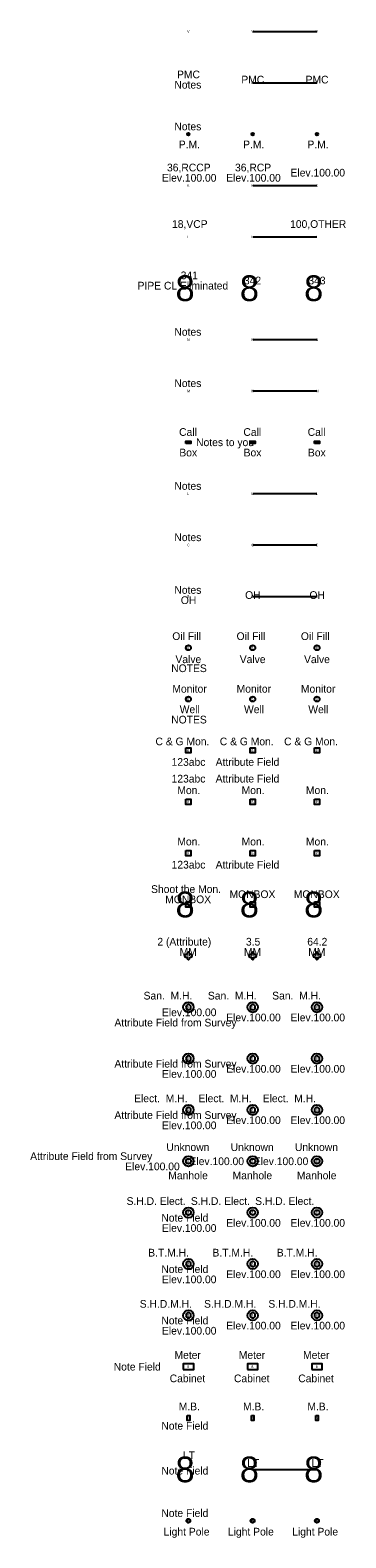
# Model space of a CAD drawing. Extents: x 40011 to 50684, y 49949 to 72236.
# Drawn here: x 50438 to 50561, y 51773 to 52360 of the extents above; entities that cross this region are included whole.
import ezdxf

# ---------------------------------------------------------------- set-up
doc = ezdxf.new("R2010")
doc.units = 0
for name, color, linetype in [('10', 7, 'Continuous'), ('12', 7, 'Continuous'), ('13', 7, 'Continuous'), ('15', 7, 'Continuous'), ('16', 7, 'Continuous'), ('17', 7, 'Continuous'), ('2', 7, 'Continuous'), ('20', 7, 'Continuous'), ('41', 7, 'Continuous'), ('44', 7, 'Continuous'), ('49', 7, 'Continuous'), ('5', 7, 'Continuous'), ('50', 7, 'Continuous'), ('56', 7, 'Continuous'), ('9', 7, 'Continuous')]:
    doc.layers.add(name, color=color, linetype=linetype)

msp = doc.modelspace()

# ---------------------------------------------------------------- linework, layer by layer
at = {"layer": '10'}
for p, q in [((50525, 52300), (50550, 52300)), ((50525, 52280), (50550, 52280))]:
    msp.add_line(p, q, dxfattribs=at)
at = {"layer": '12'}
msp.add_line((50525, 52360), (50550, 52360), dxfattribs=at)
for centre, radius in [((50500, 51940), 2), ((50525, 51940), 2), ((50550, 51940), 2), ((50500, 51900), 2), ((50500, 51900), 1), ((50525, 51900), 2), ((50525, 51900), 1), ((50550, 51900), 2), ((50550, 51900), 1)]:
    msp.add_circle(centre, radius, dxfattribs=at)
for centre, start, end in [((50500, 51940), 360, 180), ((50500, 51940), 180, 0), ((50525, 51940), 360, 180), ((50525, 51940), 180, 0), ((50550, 51940), 360, 180), ((50550, 51940), 180, 0)]:
    msp.add_arc(centre, 1, start, end, dxfattribs=at)
at = {"layer": '13'}
for centre in [(50500, 51880), (50525, 51880), (50550, 51880)]:
    msp.add_circle(centre, 2, dxfattribs=at)
for centre, start, end in [((50500, 51880), 0, 180), ((50525, 51880), 0, 180), ((50550, 51880), 0, 180), ((50500, 51880), 180, 0), ((50525, 51880), 180, 0), ((50550, 51880), 180, 0)]:
    msp.add_arc(centre, 1, start, end, dxfattribs=at)
at = {"layer": '15'}
for centre in [(50500, 52100), (50525, 52100), (50550, 52100)]:
    msp.add_circle(centre, 1, dxfattribs=at)
at = {"layer": '16'}
for centre in [(50500, 51980), (50525, 51980), (50550, 51980)]:
    msp.add_circle(centre, 2, dxfattribs=at)
for centre, start, end in [((50500, 51980), 360, 180), ((50525, 51980), 360, 180), ((50550, 51980), 360, 180), ((50500, 51980), 180, 0), ((50525, 51980), 180, 0), ((50550, 51980), 180, 0)]:
    msp.add_arc(centre, 1, start, end, dxfattribs=at)
at = {"layer": '17'}
msp.add_line((50525, 52340), (50550, 52340), dxfattribs=at)
at = {"layer": '2'}
for p, q in [((50525, 52240), (50550, 52240)), ((50525, 52220), (50550, 52220)), ((50525, 52180), (50550, 52180))]:
    msp.add_line(p, q, dxfattribs=at)
at = {"layer": '20'}
for points in [[(50497.95, 51838.95), (50502.05, 51838.95), (50502.05, 51841.05), (50497.95, 51841.05)], [(50522.95, 51838.95), (50527.05, 51838.95), (50527.05, 51841.05), (50522.95, 51841.05)], [(50547.95, 51838.95), (50552.05, 51838.95), (50552.05, 51841.05), (50547.95, 51841.05)]]:
    msp.add_lwpolyline(points, close=True, dxfattribs=at)
at = {"layer": '5'}
for p, q in [((50525, 52160), (50550, 52160)), ((50525, 52140), (50550, 52140)), ((50499.5, 52000.5), (50499, 52000.5)), ((50499, 51999.5), (50499.5, 51999.5)), ((50499.5, 52001), (50499.5, 52000.5)), ((50499.5, 51999.5), (50499.5, 51999)), ((50500.5, 52000.5), (50500.5, 52001)), ((50501, 52000.5), (50500.5, 52000.5)), ((50500.5, 51999), (50500.5, 51999.5)), ((50500.5, 51999.5), (50501, 51999.5)), ((50524.5, 52000.5), (50524, 52000.5)), ((50524, 51999.5), (50524.5, 51999.5)), ((50524.5, 52001), (50524.5, 52000.5)), ((50524.5, 51999.5), (50524.5, 51999)), ((50525.5, 52000.5), (50525.5, 52001)), ((50526, 52000.5), (50525.5, 52000.5)), ((50525.5, 51999), (50525.5, 51999.5)), ((50525.5, 51999.5), (50526, 51999.5)), ((50549.5, 52000.5), (50549, 52000.5)), ((50549, 51999.5), (50549.5, 51999.5)), ((50549.5, 52001), (50549.5, 52000.5)), ((50549.5, 51999.5), (50549.5, 51999)), ((50550.5, 52000.5), (50550.5, 52001)), ((50551, 52000.5), (50550.5, 52000.5)), ((50550.5, 51999), (50550.5, 51999.5)), ((50550.5, 51999.5), (50551, 51999.5)), ((50525, 51800), (50550, 51800))]:
    msp.add_line(p, q, dxfattribs=at)
for points in [[(50499, 52199.5), (50499, 52200.5), (50501, 52200.5), (50501, 52199.5)], [(50524, 52199.5), (50524, 52200.5), (50526, 52200.5), (50526, 52199.5)], [(50549, 52199.5), (50549, 52200.5), (50551, 52200.5), (50551, 52199.5)], [(50499, 52081), (50501, 52081), (50501, 52079), (50499, 52079)], [(50524, 52081), (50526, 52081), (50526, 52079), (50524, 52079)], [(50549, 52081), (50551, 52081), (50551, 52079), (50549, 52079)], [(50499, 52061), (50501, 52061), (50501, 52059), (50499, 52059)], [(50524, 52061), (50526, 52061), (50526, 52059), (50524, 52059)], [(50549, 52061), (50551, 52061), (50551, 52059), (50549, 52059)], [(50499, 52041), (50501, 52041), (50501, 52039), (50499, 52039)], [(50524, 52041), (50526, 52041), (50526, 52039), (50524, 52039)], [(50549, 52041), (50551, 52041), (50551, 52039), (50549, 52039)], [(50499, 52021), (50501, 52021), (50501, 52019), (50499, 52019)], [(50524, 52021), (50526, 52021), (50526, 52019), (50524, 52019)], [(50549, 52021), (50551, 52021), (50551, 52019), (50549, 52019)], [(50499.5, 51821), (50500.5, 51821), (50500.5, 51819), (50499.5, 51819)], [(50524.5, 51821), (50525.5, 51821), (50525.5, 51819), (50524.5, 51819)], [(50549.5, 51821), (50550.5, 51821), (50550.5, 51819), (50549.5, 51819)]]:
    msp.add_lwpolyline(points, close=True, dxfattribs=at)
for centre, radius in [((50500, 52320), 0.5), ((50525, 52320), 0.5), ((50550, 52320), 0.5), ((50500, 52120), 1), ((50525, 52120), 1), ((50550, 52120), 1), ((50500, 51780), 0.75), ((50525, 51780), 0.75), ((50550, 51780), 0.75)]:
    msp.add_circle(centre, radius, dxfattribs=at)
for centre, start, end in [((50499, 52000), 90, 270), ((50500, 52001), 360, 180), ((50500, 51999), 180, 0), ((50501, 52000), 270, 90), ((50524, 52000), 90, 270), ((50525, 52001), 360, 180), ((50525, 51999), 180, 0), ((50526, 52000), 270, 90), ((50549, 52000), 90, 270), ((50550, 52001), 360, 180), ((50550, 51999), 180, 0), ((50551, 52000), 270, 90)]:
    msp.add_arc(centre, 0.5, start, end, dxfattribs=at)
at = {"layer": '56'}
for centre, radius in [((50500, 51920), 2), ((50500, 51920), 1), ((50525, 51920), 2), ((50525, 51920), 1), ((50550, 51920), 2), ((50550, 51920), 1)]:
    msp.add_circle(centre, radius, dxfattribs=at)
at = {"layer": '9'}
for centre in [(50500, 51960), (50525, 51960), (50550, 51960), (50500, 51860), (50525, 51860), (50550, 51860)]:
    msp.add_circle(centre, 2, dxfattribs=at)
for centre, start, end in [((50500, 51960), 360, 180), ((50500, 51960), 180, 0), ((50525, 51960), 360, 180), ((50525, 51960), 180, 0), ((50550, 51960), 360, 180), ((50550, 51960), 180, 0), ((50500, 51860), 360, 180), ((50500, 51860), 180, 0), ((50525, 51860), 360, 180), ((50525, 51860), 180, 0), ((50550, 51860), 360, 180), ((50550, 51860), 180, 0)]:
    msp.add_arc(centre, 1, start, end, dxfattribs=at)

# ---------------------------------------------------------------- texts
at = {"layer": '12'}
for s, p in [('Elect.  M.H.', (50478.9, 51943)), ('Elect.  M.H.', (50503.9, 51943)), ('Elect.  M.H.', (50528.9, 51943)), ('S.H.D. Elect.', (50475.96, 51903)), ('S.H.D. Elect.', (50500.96, 51903)), ('S.H.D. Elect.', (50525.96, 51903))]:
    msp.add_text(s, height=3, rotation=360, dxfattribs=at).set_placement(p)
at = {"layer": '13'}
for p in [(50484.37, 51882.9), (50509.37, 51882.9), (50534.37, 51882.9)]:
    msp.add_text('B.T.M.H.', height=3, rotation=360, dxfattribs=at).set_placement(p)
at = {"layer": '15'}
for s, p in [('Monitor', (50493.76, 52102.5)), ('Monitor', (50518.76, 52102.5)), ('Monitor', (50543.76, 52102.5)), ('Well', (50496.63, 52094.5)), ('Well', (50521.63, 52094.5)), ('Well', (50546.63, 52094.5))]:
    msp.add_text(s, height=3, rotation=360, dxfattribs=at).set_placement(p)
at = {"layer": '16'}
for p in [(50482.58, 51983), (50507.58, 51983), (50532.58, 51983)]:
    msp.add_text('San.  M.H.', height=3, rotation=360, dxfattribs=at).set_placement(p)
at = {"layer": '20'}
for s, p in [('Meter', (50494.59, 51843.05)), ('Meter', (50519.59, 51843.05)), ('Meter', (50544.59, 51843.05)), ('Cabinet', (50492.72, 51833.95)), ('Cabinet', (50517.72, 51833.95)), ('Cabinet', (50542.72, 51833.95))]:
    msp.add_text(s, height=3, rotation=360, dxfattribs=at).set_placement(p)
at = {"layer": '41'}
for s, p in [('Notes', (50494.55, 52337.75)), ('PMC', (50495.58, 52341.75)), ('PMC', (50520.58, 52339.75)), ('PMC', (50545.58, 52339.75)), ('Notes', (50494.55, 52321.5)), ('Elev.100.00', (50489.72, 52301.5)), ('36,RCCP', (50491.68, 52305.5)), ('Elev.100.00', (50514.72, 52301.5)), ('36,RCP', (50518.13, 52305.5)), ('Elev.100.00', (50539.72, 52303.5)), ('18,VCP', (50493.63, 52283.5)), ('100,OTHER', (50539.54, 52283.5)), ('Notes', (50494.55, 52241.5)), ('Notes', (50494.55, 52221.5)), ('Notes to you', (50503, 52198.5)), ('Notes', (50494.55, 52181.5)), ('Notes', (50494.55, 52161.5)), ('Notes', (50494.55, 52141)), ('OH', (50497.06, 52137)), ('OH', (50522.06, 52139)), ('OH', (50547.06, 52139)), ('NOTES', (50493.32, 52110.5)), ('NOTES', (50493.32, 52090.5)), ('Shoot the Mon.', (50485.49, 52024.5)), ('MONBOX', (50490.99, 52020.5)), ('MONBOX', (50515.99, 52022.5)), ('MONBOX', (50540.99, 52022.5)), ('2 (Attribute)', (50487.93, 52004)), ('3.5', (50522.37, 52004)), ('64.2', (50546.22, 52004)), ('MM', (50496.59, 52000)), ('MM', (50521.59, 52000)), ('MM', (50546.59, 52000)), ('Attribute Field from Survey', (50471.24, 51972.5)), ('Elev.100.00', (50489.72, 51976.5)), ('Elev.100.00', (50514.72, 51974.5)), ('Elev.100.00', (50539.72, 51974.5)), ('Attribute Field from Survey', (50471.24, 51956.5)), ('Elev.100.00', (50514.72, 51954.5)), ('Elev.100.00', (50539.72, 51954.5)), ('Elev.100.00', (50489.72, 51952.5)), ('Attribute Field from Survey', (50471.24, 51936.5)), ('Elev.100.00', (50489.72, 51932.5)), ('Elev.100.00', (50514.72, 51934.5)), ('Elev.100.00', (50539.72, 51934.5)), ('Attribute Field from Survey', (50438.48, 51920.5)), ('Elev.100.00', (50475.44, 51916.5)), ('Elev.100.00', (50500.44, 51918.5)), ('Elev.100.00', (50525.44, 51918.5)), ('Note Field', (50489.48, 51896.5)), ('Elev.100.00', (50489.72, 51892.5)), ('Elev.100.00', (50514.72, 51894.5)), ('Elev.100.00', (50539.72, 51894.5)), ('Note Field', (50489.48, 51876.5)), ('Elev.100.00', (50489.72, 51872.5)), ('Elev.100.00', (50514.72, 51874.5)), ('Elev.100.00', (50539.72, 51874.5)), ('Note Field', (50489.48, 51856.5)), ('Elev.100.00', (50514.72, 51854.5)), ('Elev.100.00', (50539.72, 51854.5)), ('Elev.100.00', (50489.72, 51852.5)), ('Note Field', (50470.97, 51838.5)), ('Note Field', (50489.48, 51815.5)), ('LT', (50497.85, 51804)), ('Note Field', (50489.48, 51798)), ('LT', (50522.85, 51801)), ('LT', (50547.85, 51801)), ('Note Field', (50489.48, 51781.5))]:
    msp.add_text(s, height=3, dxfattribs=at).set_placement(p)
at = {"layer": '44'}
for s, height, p in [('8', 1, (50499.5, 52319.5)), ('8', 1, (50524.5, 52319.5)), ('8', 1, (50549.5, 52319.5)), ('K', 1, (50499.5, 52299.5)), ('K', 1, (50524.5, 52299.5)), ('K', 1, (50549.5, 52299.5)), ('I', 1, (50499.5, 52279.5)), ('I', 1, (50524.5, 52279.5)), ('I', 1, (50549.5, 52279.5)), ('N', 1, (50499.47, 52239.5)), ('N', 1, (50524.47, 52239.5)), ('N', 1, (50549.47, 52239.5)), ('M', 1, (50499.5, 52219.5)), ('M', 1, (50524.5, 52219.5)), ('M', 1, (50549.5, 52219.5)), ('8', 1, (50499.5, 52199.5)), ('8', 1, (50524.5, 52199.5)), ('8', 1, (50549.5, 52199.5)), ('L', 1, (50499.5, 52179.5)), ('L', 1, (50524.5, 52179.5)), ('L', 1, (50549.5, 52179.5)), ('C', 1, (50499.5, 52159.5)), ('C', 1, (50524.5, 52159.5)), ('C', 1, (50549.5, 52159.5)), ('8', 1, (50499.5, 52139.5)), ('8', 1, (50524.5, 52139.5)), ('8', 1, (50549.5, 52139.5)), ('8', 1, (50499.5, 52119.5)), ('8', 1, (50524.5, 52119.5)), ('8', 1, (50549.5, 52119.5)), ('8', 1, (50499.5, 52099.5)), ('8', 1, (50524.5, 52099.5)), ('8', 1, (50549.5, 52099.5)), ('8', 1, (50499.5, 52079.5)), ('8', 1, (50524.5, 52079.5)), ('8', 1, (50549.5, 52079.5)), ('8', 1, (50499.5, 52059.5)), ('8', 1, (50524.5, 52059.5)), ('8', 1, (50549.5, 52059.5)), ('8', 1, (50499.5, 52039.5)), ('8', 1, (50524.5, 52039.5)), ('8', 1, (50549.5, 52039.5)), ('8', 10, (50495, 52015)), ('8', 10, (50520, 52015)), ('8', 10, (50545, 52015)), ('8', 1, (50499.5, 51999.5)), ('8', 1, (50524.5, 51999.5)), ('8', 1, (50549.5, 51999.5)), ('8', 1, (50499.5, 51979.5)), ('8', 1, (50524.5, 51979.5)), ('8', 1, (50549.5, 51979.5)), ('8', 1, (50499.5, 51959.5)), ('8', 1, (50524.5, 51959.5)), ('8', 1, (50549.5, 51959.5)), ('8', 1, (50499.5, 51939.5)), ('8', 1, (50524.5, 51939.5)), ('8', 1, (50549.5, 51939.5)), ('8', 1, (50499.5, 51919.5)), ('8', 1, (50524.5, 51919.5)), ('8', 1, (50549.5, 51919.5)), ('8', 1, (50499.5, 51899.5)), ('8', 1, (50524.5, 51899.5)), ('8', 1, (50549.5, 51899.5)), ('8', 1, (50499.5, 51879.5)), ('8', 1, (50524.5, 51879.5)), ('8', 1, (50549.5, 51879.5)), ('8', 1, (50499.5, 51859.5)), ('8', 1, (50524.5, 51859.5)), ('8', 1, (50549.5, 51859.5)), ('8', 1, (50499.5, 51839.5)), ('8', 1, (50524.5, 51839.5)), ('8', 1, (50549.5, 51839.5)), ('8', 0.5, (50499.75, 51819.75)), ('8', 0.5, (50524.75, 51819.75)), ('8', 0.5, (50549.75, 51819.75)), ('8', 10, (50495, 51795)), ('8', 10, (50520, 51795)), ('8', 10, (50545, 51795))]:
    msp.add_text(s, height=height, dxfattribs=at).set_placement(p)
at = {"layer": '49'}
for s, p in [('V', (50499.5, 52359.5)), ('V', (50524.5, 52359.5)), ('V', (50549.5, 52359.5)), ('8', (50499.5, 52339.5)), ('8', (50524.5, 52339.5)), ('8', (50549.5, 52339.5))]:
    msp.add_text(s, height=1, dxfattribs=at).set_placement(p)
at = {"layer": '5'}
for s, p in [('P.M.', (50496.28, 52314.5)), ('P.M.', (50521.28, 52314.5)), ('P.M.', (50546.28, 52314.5)), ('Call', (50496.38, 52202.5)), ('Call', (50521.38, 52202.5)), ('Call', (50546.38, 52202.5)), ('Box', (50496.48, 52194.5)), ('Box', (50521.48, 52194.5)), ('Box', (50546.48, 52194.5)), ('Oil Fill', (50493.74, 52123)), ('Oil Fill', (50518.74, 52123)), ('Oil Fill', (50543.74, 52123)), ('Valve', (50494.97, 52114)), ('Valve', (50519.97, 52114)), ('Valve', (50544.97, 52114)), ('C & G Mon.', (50487.21, 52082)), ('C & G Mon.', (50512.21, 52082)), ('C & G Mon.', (50537.21, 52082)), ('Mon.', (50495.7, 52063)), ('Mon.', (50520.7, 52063)), ('Mon.', (50545.7, 52063)), ('Mon.', (50495.7, 52043)), ('Mon.', (50520.7, 52043)), ('Mon.', (50545.7, 52043)), ('M.B.', (50496.25, 51823)), ('M.B.', (50521.25, 51823)), ('M.B.', (50546.25, 51823)), ('Light Pole', (50490.37, 51774.25)), ('Light Pole', (50515.37, 51774.25)), ('Light Pole', (50540.37, 51774.25))]:
    msp.add_text(s, height=3, rotation=360, dxfattribs=at).set_placement(p)
for s, p in [('123abc', (50493.46, 52074)), ('Attribute Field', (50510.6, 52074)), ('123abc', (50493.46, 52067.5)), ('Attribute Field', (50510.6, 52067.5)), ('123abc', (50493.46, 52034)), ('Attribute Field', (50510.6, 52034)), ('+', (50498.55, 51778.5)), ('+', (50523.55, 51778.5)), ('+', (50548.55, 51778.5))]:
    msp.add_text(s, height=3, dxfattribs=at).set_placement(p)
at = {"layer": '50'}
for s, height, p in [('PIPE CL Eliminated', 3, (50480.24, 52259.5)), ('8', 10, (50495, 52255)), ('341', 3, (50497.01, 52263.5)), ('8', 10, (50520, 52255)), ('342', 3, (50521.59, 52261.5)), ('8', 10, (50545, 52255)), ('343', 3, (50546.65, 52261.5))]:
    msp.add_text(s, height=height, dxfattribs=at).set_placement(p)
at = {"layer": '56'}
for s, p in [('Unknown', (50491.43, 51924)), ('Unknown', (50516.43, 51924)), ('Unknown', (50541.43, 51924)), ('Manhole', (50492.18, 51913)), ('Manhole', (50517.18, 51913)), ('Manhole', (50542.18, 51913))]:
    msp.add_text(s, height=3, rotation=360, dxfattribs=at).set_placement(p)
at = {"layer": '9'}
for p in [(50481.09, 51862.97), (50506.09, 51862.97), (50531.09, 51862.97)]:
    msp.add_text('S.H.D.M.H.', height=3, rotation=360, dxfattribs=at).set_placement(p)

doc.saveas('drawing.dxf')
